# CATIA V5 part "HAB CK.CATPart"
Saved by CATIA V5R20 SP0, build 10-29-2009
Part number: HAB CK
Bounding box of the stored display mesh (mm): x 0 to 10, y 189.738 to 350.657, z -6.288 to 441.066
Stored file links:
  D:\Dropbox\IAO_2012\IAO_2012_766_vlaroche\vlaroche\vlaroche\IAO\A rendre\HAB CK.CATPart
  D:\Catia\IAO\A rendre\Assemblage.CATProduct
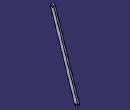
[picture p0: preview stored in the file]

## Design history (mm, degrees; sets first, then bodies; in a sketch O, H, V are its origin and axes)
Set1
  Point1: linked copy from another document
  Point2: linked copy from another document
Body1 (main body)
  Sketch1 on yz-plane, origin (0, 0, 0), H (0, 1, 0), V (0, 0, 1)
    construction line L1 (199.7278, 431.0686) -> (340.6677, 3.7093)
    point P1 (199.7278, 431.0686)
    point P2 (340.6677, 3.7093)
    line L2 (209.2247, 434.2006) -> (350.1645, 6.8413)
    line L3 (331.1708, 0.5773) -> (190.2309, 427.9366)
    arc A1 centre (340.6677, 3.7093) radius 10 from (350.1645, 6.8413) to (331.1708, 0.5773) cw
    arc A2 centre (199.7278, 431.0686) radius 10 from (190.2309, 427.9366) to (209.2247, 434.2006) cw
    reference projected point E1 (199.7278, 431.0686) from Point1
    reference projected point E2 (340.6677, 3.7093) from Point2
    circle A3 centre (340.6677, 3.7093) radius 5
    circle A4 centre (199.7278, 431.0686) radius 5
    distance L1 L2 = 10
    radius A3 = 5
    radius A4 = 5
    tangency: A1 L2, A2 L2, A1 L3, A2 L3
    coincidence: E1 P1, P2 E2
  Pad1: profile Sketch1, direction (1, 0, 0), length 10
